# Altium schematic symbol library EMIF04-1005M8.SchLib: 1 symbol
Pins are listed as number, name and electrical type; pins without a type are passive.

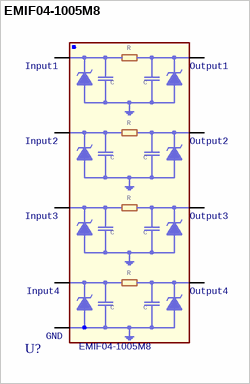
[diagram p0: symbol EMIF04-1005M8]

## EMIF04-1005M8
designator U?
footprint ST_QFN40P170X150X55-9L
pins: 1 Input1, 2 Input2, 3 Input3, 4 Input4, 5 Output4, 6 Output3, 7 Output2, 8 Output1, 9 GND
